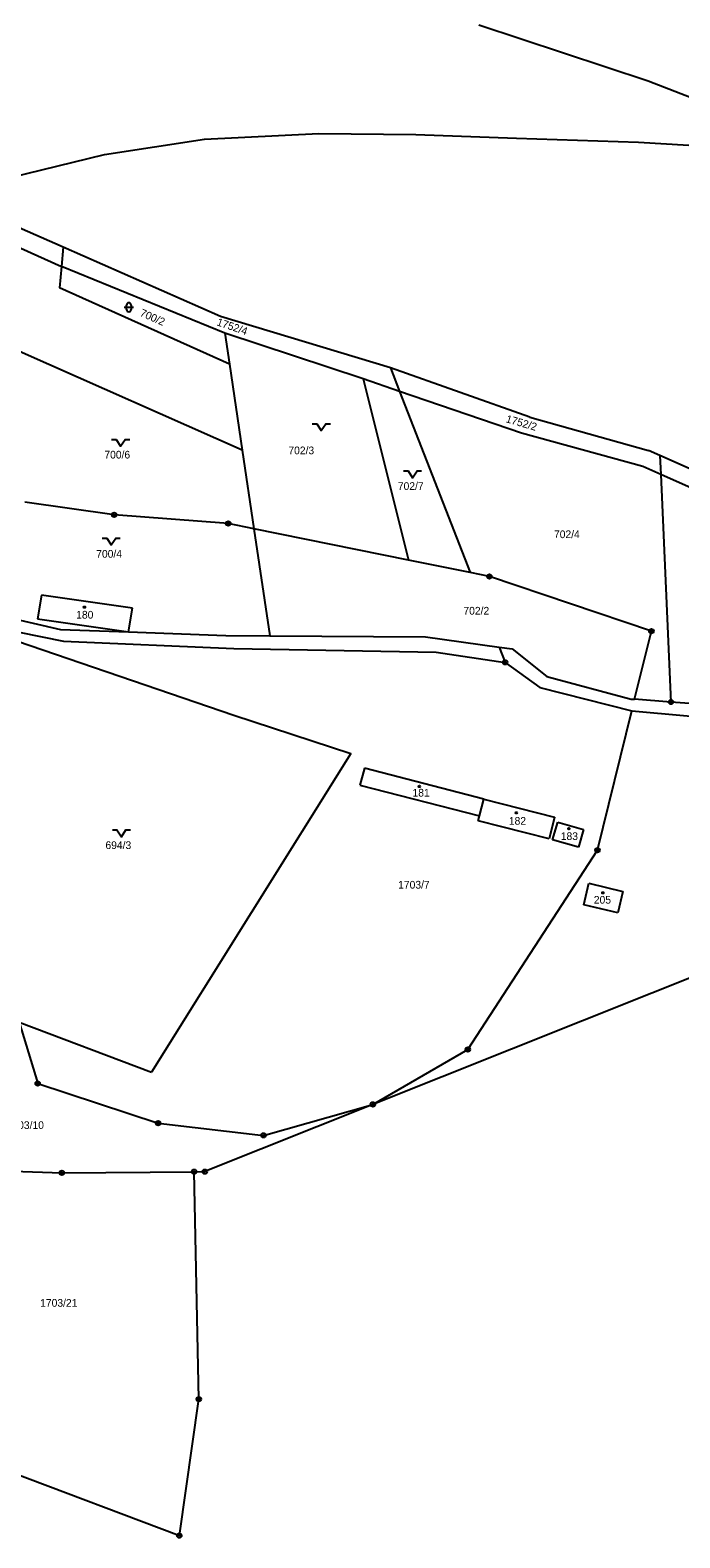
# Model space of a CAD drawing. Extents: x -546762 to -540209, y -1046851 to -1035694.
# Drawn here: x -543689.8 to -543546.4, y -1042760.2 to -1042427.6 of the extents above; entities that cross this region are included whole.
import ezdxf

# ---------------------------------------------------------------- set-up
doc = ezdxf.new("R2010")
doc.units = 0
for name, color, linetype in [('Vrstva 1', 7, 'Continuous'), ('Vrstva 18', 7, 'Continuous'), ('Vrstva 19', 7, 'Continuous'), ('Vrstva 24', 7, 'Continuous'), ('Vrstva 25', 7, 'Continuous'), ('Vrstva 3', 7, 'Continuous'), ('Vrstva 37', 7, 'Continuous'), ('Vrstva 52', 7, 'Continuous'), ('Vrstva 6', 7, 'Continuous')]:
    doc.layers.add(name, color=color, linetype=linetype)

msp = doc.modelspace()

# ---------------------------------------------------------------- linework, layer by layer
at = {"layer": 'Vrstva 1'}
for points in [[(-543682.57, -1042475.53), (-543682.95, -1042479.73)], [(-543647.81, -1042490.79), (-543682.57, -1042475.53)], [(-543682.95, -1042479.73), (-543683.37, -1042484.46)], [(-543646.85, -1042494.45), (-543682.95, -1042479.73)], [(-543645.83, -1042501.33), (-543683.37, -1042484.46)], [(-543610.3, -1042502.14), (-543647.81, -1042490.79)], [(-543616.31, -1042504.56), (-543646.85, -1042494.45)], [(-543646.85, -1042494.45), (-543645.83, -1042501.33)], [(-543643.01, -1042520.26), (-543691.54, -1042498.84)], [(-543645.83, -1042501.33), (-543643.01, -1042520.26)], [(-543579.57, -1042512.98), (-543610.3, -1042502.14)], [(-543610.3, -1042502.14), (-543608.28, -1042507.31)], [(-543608.28, -1042507.31), (-543616.31, -1042504.56)], [(-543581.39, -1042516.54), (-543608.28, -1042507.31)], [(-543608.28, -1042507.31), (-543592.72, -1042547.27)], [(-543579.57, -1042512.98), (-543553.34, -1042520.35)], [(-543554.61, -1042523.89), (-543581.39, -1042516.54)], [(-543643.01, -1042520.26), (-543640.43, -1042537.6)], [(-543550.85, -1042521.45), (-543553.34, -1042520.35)], [(-543550.66, -1042525.64), (-543554.61, -1042523.89)], [(-543512, -1042538.63), (-543550.85, -1042521.45)], [(-543550.85, -1042521.45), (-543550.66, -1042525.64)], [(-543507.43, -1042544.83), (-543550.66, -1042525.64)], [(-543550.66, -1042525.64), (-543548.41, -1042575.83)], [(-543671.28, -1042534.53), (-543691.01, -1042531.78)], [(-543646.11, -1042536.45), (-543671.28, -1042534.53)], [(-543640.43, -1042537.6), (-543646.11, -1042536.45)], [(-543640.43, -1042537.6), (-543636.91, -1042561.21)], [(-543606.34, -1042544.51), (-543640.43, -1042537.6)], [(-543592.72, -1042547.27), (-543606.34, -1042544.51)], [(-543588.49, -1042548.13), (-543592.72, -1042547.27)], [(-543552.72, -1042560.21), (-543588.49, -1042548.13)], [(-543687.34, -1042552.26), (-543688.18, -1042557.49)], [(-543667.28, -1042555.15), (-543687.34, -1042552.26)], [(-543707.2, -1042557.44), (-543682.5, -1042562.38)], [(-543701.3, -1042555.64), (-543683.15, -1042559.84)], [(-543688.18, -1042557.49), (-543668.11, -1042560.38)], [(-543668.11, -1042560.38), (-543667.28, -1042555.15)], [(-543701.06, -1042559.54), (-543644.86, -1042578.71)], [(-543683.15, -1042559.84), (-543668.11, -1042560.38)], [(-543668.11, -1042560.38), (-543646.62, -1042561.14)], [(-543556.42, -1042575.24), (-543552.72, -1042560.21)], [(-543682.5, -1042562.38), (-543644.91, -1042564.02)], [(-543646.62, -1042561.14), (-543636.91, -1042561.21)], [(-543644.91, -1042564.02), (-543600.21, -1042564.84)], [(-543636.91, -1042561.21), (-543602.6, -1042561.45)], [(-543602.6, -1042561.45), (-543586.31, -1042563.72)], [(-543586.31, -1042563.72), (-543583.45, -1042564.12)], [(-543583.45, -1042564.12), (-543575.78, -1042570.21)], [(-543600.21, -1042564.84), (-543585, -1042567.08)], [(-543585, -1042567.08), (-543577.36, -1042572.66)], [(-543575.78, -1042570.21), (-543557.18, -1042575.19)], [(-543577.36, -1042572.66), (-543557.05, -1042577.79)], [(-543557.18, -1042575.19), (-543556.42, -1042575.24)], [(-543548.41, -1042575.83), (-543556.42, -1042575.24)], [(-543522.7, -1042577.71), (-543548.41, -1042575.83)], [(-543644.86, -1042578.71), (-543619.09, -1042587.16)], [(-543564.62, -1042608.51), (-543557.05, -1042577.79)], [(-543557.05, -1042577.79), (-543522.03, -1042580.92)], [(-543619.09, -1042587.16), (-543663.02, -1042657.52)], [(-543616.02, -1042590.45), (-543617.09, -1042594.21)], [(-543589.67, -1042597.25), (-543616.02, -1042590.45)], [(-543617.09, -1042594.21), (-543590.67, -1042600.97)], [(-543590.67, -1042600.97), (-543589.67, -1042597.25)], [(-543589.67, -1042597.25), (-543574.08, -1042601.23)], [(-543590.94, -1042602.03), (-543590.67, -1042600.97)], [(-543575.31, -1042606.03), (-543590.94, -1042602.03)], [(-543574.08, -1042601.23), (-543575.31, -1042606.03)], [(-543574.52, -1042606.23), (-543573.39, -1042602.33)], [(-543573.39, -1042602.33), (-543567.69, -1042603.93)], [(-543567.69, -1042603.93), (-543568.79, -1042607.84)], [(-543568.79, -1042607.84), (-543574.52, -1042606.23)], [(-543593.23, -1042652.48), (-543564.62, -1042608.51)], [(-543567.65, -1042620.59), (-543566.54, -1042615.81)], [(-543566.54, -1042615.81), (-543559, -1042617.62)], [(-543560.13, -1042622.37), (-543567.65, -1042620.59)], [(-543559, -1042617.62), (-543560.13, -1042622.37)], [(-543537.32, -1042633.92), (-543614.18, -1042664.6)], [(-543692.29, -1042646.49), (-543663.02, -1042657.52)], [(-543692.29, -1042646.49), (-543688.16, -1042659.98)], [(-543614.18, -1042664.6), (-543593.23, -1042652.48)], [(-543688.16, -1042659.98), (-543661.57, -1042668.75)], [(-543614.18, -1042664.6), (-543651.3, -1042679.42)], [(-543638.33, -1042671.42), (-543614.18, -1042664.6)], [(-543661.57, -1042668.75), (-543638.33, -1042671.42)], [(-543693.55, -1042679.34), (-543682.85, -1042679.68)], [(-543682.85, -1042679.68), (-543653.62, -1042679.44)], [(-543653.62, -1042679.44), (-543651.3, -1042679.42)], [(-543652.6, -1042729.61), (-543653.62, -1042679.44)], [(-543769.3, -1042717.35), (-543656.9, -1042759.71)], [(-543656.9, -1042759.71), (-543652.6, -1042729.61)]]:
    msp.add_lwpolyline(points, dxfattribs=at)
at = {"layer": 'Vrstva 24'}
for centre, radius in [((-543671.28, -1042534.53), 0.5), ((-543671.28, -1042534.53), 0.1), ((-543646.11, -1042536.45), 0.5), ((-543646.11, -1042536.45), 0.1), ((-543588.49, -1042548.13), 0.5), ((-543588.49, -1042548.13), 0.1), ((-543552.72, -1042560.21), 0.5), ((-543552.72, -1042560.21), 0.1), ((-543585, -1042567.08), 0.5), ((-543585, -1042567.08), 0.1), ((-543548.41, -1042575.83), 0.5), ((-543548.41, -1042575.83), 0.1), ((-543564.62, -1042608.51), 0.5), ((-543564.62, -1042608.51), 0.1), ((-543593.23, -1042652.48), 0.5), ((-543593.23, -1042652.48), 0.1), ((-543688.16, -1042659.98), 0.5), ((-543688.16, -1042659.98), 0.1), ((-543614.18, -1042664.6), 0.5), ((-543614.18, -1042664.6), 0.1), ((-543661.57, -1042668.75), 0.5), ((-543661.57, -1042668.75), 0.1), ((-543638.33, -1042671.42), 0.5), ((-543638.33, -1042671.42), 0.1), ((-543682.85, -1042679.68), 0.5), ((-543682.85, -1042679.68), 0.1), ((-543653.62, -1042679.44), 0.5), ((-543653.62, -1042679.44), 0.1), ((-543651.3, -1042679.42), 0.5), ((-543651.3, -1042679.42), 0.1), ((-543652.6, -1042729.61), 0.5), ((-543652.6, -1042729.61), 0.1), ((-543656.9, -1042759.71), 0.5), ((-543656.9, -1042759.71), 0.1)]:
    msp.add_circle(centre, radius, dxfattribs=at)
at = {"layer": 'Vrstva 25'}
for p, q in [((-543669.05, -1042488.76), (-543667.05, -1042488.76)), ((-543668.55, -1042489.26), (-543668.55, -1042488.26)), ((-543667.55, -1042488.26), (-543667.55, -1042489.26))]:
    msp.add_line(p, q, dxfattribs=at)
for points in [[(-543627.58, -1042514.46), (-543626.58, -1042514.46), (-543625.58, -1042515.96), (-543624.58, -1042514.46), (-543623.58, -1042514.46)], [(-543671.86, -1042517.92), (-543670.86, -1042517.92), (-543669.86, -1042519.42), (-543668.86, -1042517.92), (-543667.86, -1042517.92)], [(-543607.43, -1042524.85), (-543606.43, -1042524.85), (-543605.43, -1042526.35), (-543604.43, -1042524.85), (-543603.43, -1042524.85)], [(-543673.94, -1042539.68), (-543672.94, -1042539.68), (-543671.94, -1042541.18), (-543670.94, -1042539.68), (-543669.94, -1042539.68)], [(-543671.68, -1042604.06), (-543670.68, -1042604.06), (-543669.68, -1042605.56), (-543668.68, -1042604.06), (-543667.68, -1042604.06)]]:
    msp.add_lwpolyline(points, dxfattribs=at)
for centre in [(-543677.85, -1042554.91), (-543603.93, -1042594.46), (-543582.53, -1042600.27), (-543570.94, -1042603.77), (-543563.44, -1042617.93)]:
    msp.add_circle(centre, 0.175, dxfattribs=at)
for centre, start, end in [((-543668.05, -1042488.26), 0, 180), ((-543668.05, -1042489.26), 180, 0)]:
    msp.add_arc(centre, 0.5, start, end, dxfattribs=at)
at = {"layer": 'Vrstva 3'}
for points in [[(-543687.34, -1042552.26), (-543688.18, -1042557.49)], [(-543667.28, -1042555.15), (-543687.34, -1042552.26)], [(-543688.18, -1042557.49), (-543668.11, -1042560.38)], [(-543668.11, -1042560.38), (-543667.28, -1042555.15)], [(-543616.02, -1042590.45), (-543617.09, -1042594.21)], [(-543589.67, -1042597.25), (-543616.02, -1042590.45)], [(-543617.09, -1042594.21), (-543590.67, -1042600.97)], [(-543590.67, -1042600.97), (-543589.67, -1042597.25)], [(-543590.67, -1042600.97), (-543589.67, -1042597.25)], [(-543589.67, -1042597.25), (-543574.08, -1042601.23)], [(-543590.94, -1042602.03), (-543590.67, -1042600.97)], [(-543575.31, -1042606.03), (-543590.94, -1042602.03)], [(-543574.08, -1042601.23), (-543575.31, -1042606.03)], [(-543574.52, -1042606.23), (-543573.39, -1042602.33)], [(-543573.39, -1042602.33), (-543567.69, -1042603.93)], [(-543567.69, -1042603.93), (-543568.79, -1042607.84)], [(-543568.79, -1042607.84), (-543574.52, -1042606.23)], [(-543567.65, -1042620.59), (-543566.54, -1042615.81)], [(-543566.54, -1042615.81), (-543559, -1042617.62)], [(-543560.13, -1042622.37), (-543567.65, -1042620.59)], [(-543559, -1042617.62), (-543560.13, -1042622.37)]]:
    msp.add_lwpolyline(points, dxfattribs=at)
at = {"layer": 'Vrstva 37'}
for centre in [(-543677.85, -1042554.91), (-543603.93, -1042594.46), (-543582.53, -1042600.27), (-543570.94, -1042603.77), (-543563.44, -1042617.93)]:
    msp.add_circle(centre, 0.175, dxfattribs=at)
at = {"layer": 'Vrstva 52'}
for points in [[(-543739.84, -1042477.33), (-543716.42, -1042467.37), (-543694.17, -1042460.16), (-543673.4, -1042455.07), (-543651.36, -1042451.67), (-543626.13, -1042450.4), (-543604.73, -1042450.61), (-543582.48, -1042451.46), (-543555.56, -1042452.31), (-543534.58, -1042453.58), (-543520.38, -1042453.58), (-543509.36, -1042452.52), (-543500.76, -1042451.67), (-543493.37, -1042450.71), (-543489.01, -1042450.46)], [(-543483.19, -1042553.62), (-543507.43, -1042544.83), (-543550.66, -1042525.64), (-543554.61, -1042523.89), (-543581.39, -1042516.54), (-543608.28, -1042507.31), (-543616.31, -1042504.56), (-543646.85, -1042494.45), (-543645.83, -1042501.33), (-543643.01, -1042520.26), (-543691.54, -1042498.84), (-543739.84, -1042477.33)]]:
    msp.add_lwpolyline(points, dxfattribs=at)
at = {"layer": 'Vrstva 6'}
for points in [[(-543590.82, -1042426.46), (-543553.42, -1042438.83)], [(-543553.42, -1042438.83), (-543497.81, -1042460.35)], [(-543711.38, -1042467), (-543682.95, -1042479.73)], [(-543682.57, -1042475.53), (-543706.26, -1042465.14)], [(-543616.31, -1042504.56), (-543606.34, -1042544.51)], [(-543586.31, -1042563.72), (-543585, -1042567.08)]]:
    msp.add_lwpolyline(points, dxfattribs=at)

# ---------------------------------------------------------------- texts
at = {"layer": 'Vrstva 18'}
for s, rotation, p in [('700/2', 336.2851, (-543665.75, -1042490.6)), ('1752/4', 341.311, (-543648.79, -1042492.7)), ('1752/2', 343.82, (-543584.97, -1042514.09))]:
    msp.add_text(s, height=1.7, rotation=rotation, dxfattribs=at).set_placement(p)
for s, p in [('700/6', (-543673.45, -1042522.12)), ('702/3', (-543632.84, -1042521.18)), ('702/7', (-543608.68, -1042529.05)), ('702/4', (-543574.22, -1042539.68)), ('700/4', (-543675.25, -1042544)), ('702/2', (-543594.21, -1042556.55)), ('694/3', (-543673.21, -1042608.26)), ('1703/7', (-543608.61, -1042616.99)), ('1703/10', (-543695.01, -1042670.02)), ('1703/21', (-543687.62, -1042709.23))]:
    msp.add_text(s, height=1.7, dxfattribs=at).set_placement(p)
at = {"layer": 'Vrstva 19'}
for s, p in [('180', (-543679.67, -1042557.43)), ('181', (-543605.45, -1042596.69)), ('182', (-543584.18, -1042602.9)), ('183', (-543572.72, -1042606.27)), ('205', (-543565.43, -1042620.31))]:
    msp.add_text(s, height=1.7, dxfattribs=at).set_placement(p)

doc.saveas('drawing.dxf')
